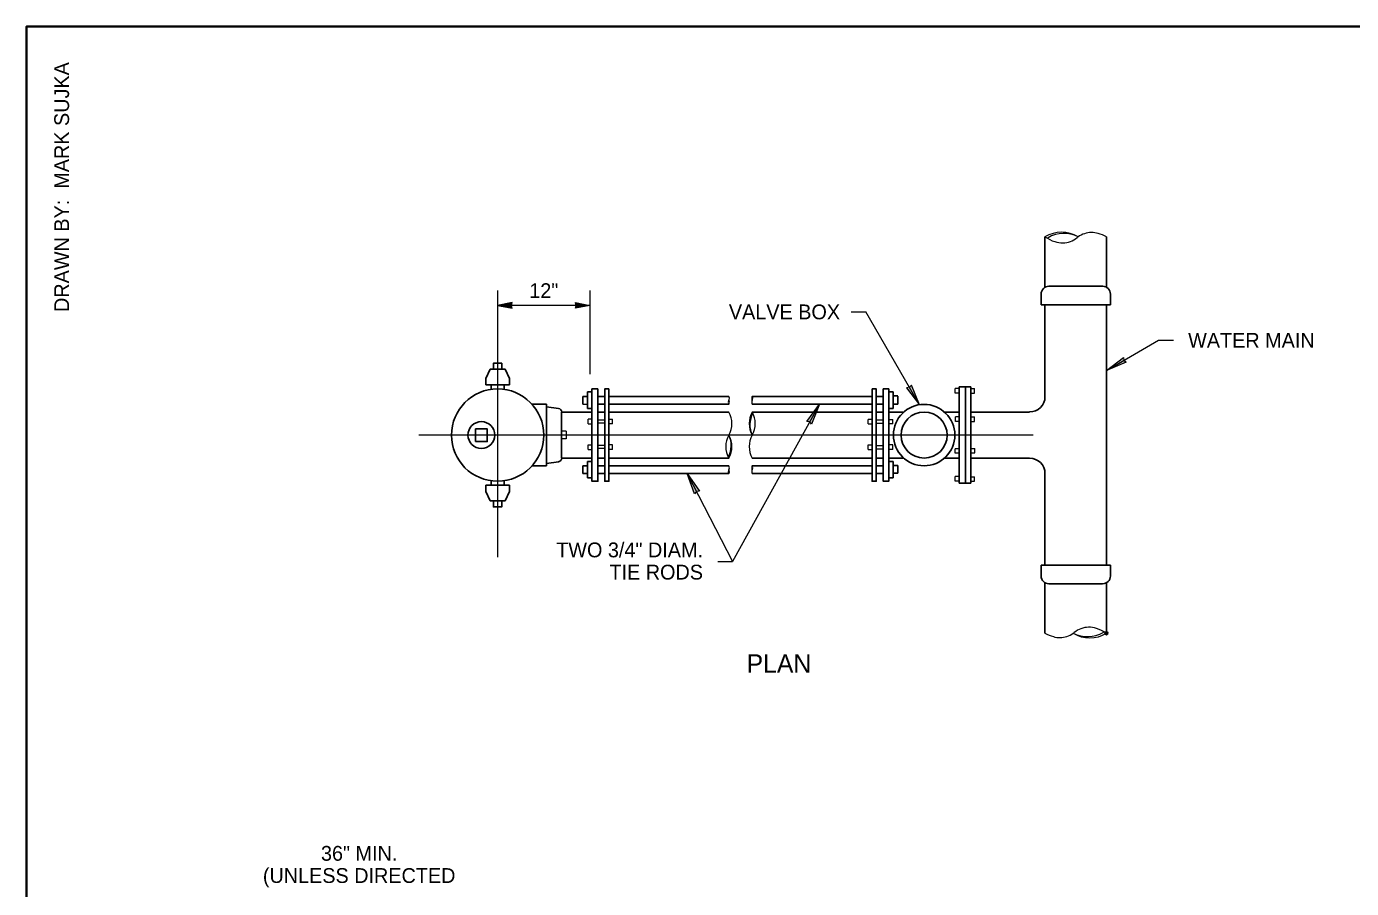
# Model space of a CAD drawing. Extents: x 99860 to 103153, y 99998 to 102077.
# Drawn here: x 99862 to 101294, y 101144 to 102076 of the extents above; entities that cross this region are included whole.
import ezdxf
from ezdxf.enums import TextEntityAlignment as Align

# ---------------------------------------------------------------- set-up
doc = ezdxf.new("R2010")
doc.units = 0
doc.header["$LTSCALE"] = 6.4
doc.header["$PDMODE"] = 32
doc.header["$PDSIZE"] = 3.2
for name, color, linetype, lineweight in [('1', 7, 'Continuous', 25), ('15', 7, 'Continuous', 13), ('18', 7, 'Continuous', 13), ('20', 7, 'Continuous', 13), ('6', 7, 'Continuous', 25)]:
    doc.layers.add(name, color=color, linetype=linetype, lineweight=lineweight)
doc.layers.add('62', color=7, linetype='Continuous')

msp = doc.modelspace()

# ---------------------------------------------------------------- hatches: boundary and pattern name
at = {"layer": '15'}
for points in [[(100371.007, 101774.168), (100386.732, 101771.084), (100386.004, 101774.168), (100386.732, 101777.252)], [(100470.757, 101774.168), (100455.032, 101771.084), (100455.76, 101774.168), (100455.032, 101777.252)], [(101028.745, 101704.029), (101047.023, 101718.028), (101047.599, 101714.914), (101050.008, 101712.858)], [(100826.834, 101666.996), (100818.004, 101688.259), (100815.947, 101685.852), (100812.834, 101685.274)], [(100718.66, 101667.48), (100710.239, 101646.052), (100708.136, 101648.419), (100705.013, 101648.937)], [(100575.94, 101592.518), (100589.049, 101573.59), (100585.912, 101573.162), (100583.742, 101570.856)]]:
    msp.add_hatch(color=256, dxfattribs=at).paths.add_polyline_path(points)

# ---------------------------------------------------------------- linework, layer by layer
at = {"layer": '1', "lineweight": 35}
msp.add_lwpolyline([(99862, 99999.5), (103151, 99999.5), (103151, 102075.5), (99862, 102075.5)], close=True, dxfattribs=at)
at = {"layer": '15'}
for p, q in [((100371.007, 101790.168), (100371.007, 101502.38)), ((100470.757, 101790.168), (100470.757, 101700.105)), ((100470.757, 101774.168), (100371.007, 101774.168)), ((100752.967, 101767.226), (100768.967, 101767.226)), ((100826.834, 101666.996), (100768.967, 101767.226)), ((101028.745, 101704.029), (101085.037, 101736.529)), ((101085.037, 101736.529), (101101.037, 101736.529)), ((100718.66, 101667.48), (100624.853, 101497.568)), ((100285.793, 101634.268), (100949.745, 101634.268)), ((100575.94, 101592.518), (100624.853, 101497.568)), ((100608.853, 101497.568), (100624.853, 101497.568))]:
    msp.add_line(p, q, dxfattribs=at)
for points in [[(100371.007, 101774.168), (100386.732, 101771.084), (100386.004, 101774.168), (100386.732, 101777.252)], [(100470.757, 101774.168), (100455.032, 101771.084), (100455.76, 101774.168), (100455.032, 101777.252)], [(101028.745, 101704.029), (101047.023, 101718.028), (101047.599, 101714.914), (101050.008, 101712.858)], [(100826.834, 101666.996), (100818.004, 101688.259), (100815.947, 101685.852), (100812.834, 101685.274)], [(100718.66, 101667.48), (100710.239, 101646.052), (100708.136, 101648.419), (100705.013, 101648.937)], [(100575.94, 101592.518), (100589.049, 101573.59), (100585.912, 101573.162), (100583.742, 101570.856)]]:
    msp.add_lwpolyline(points, close=True, dxfattribs=at)
at = {"layer": '18', "lineweight": 25}
for p, q in [((100358.232, 101695.455), (100362.77, 101705.293)), ((100358.232, 101688.268), (100358.232, 101695.455)), ((100379.27, 101705.293), (100362.77, 101705.293)), ((100383.77, 101688.268), (100358.232, 101688.268)), ((100363.845, 101683.542), (100363.845, 101688.268)), ((100378.195, 101683.54), (100378.195, 101688.268)), ((100869.72, 101582.405), (100869.72, 101686.143)), ((100869.72, 101686.143), (100882.207, 101686.143)), ((100876.345, 101582.405), (100876.345, 101686.143)), ((100882.207, 101582.405), (100882.207, 101686.143)), ((100408.22, 101667.48), (100423.707, 101667.48)), ((100423.707, 101667.48), (100423.707, 101601.03)), ((100463.207, 101675.993), (100468.232, 101675.993)), ((100463.207, 101675.743), (100463.207, 101667.48)), ((100468.232, 101680.868), (100468.232, 101663.043)), ((100468.232, 101680.868), (100472.882, 101680.868)), ((100479.27, 101675.993), (100486.707, 101675.993)), ((100479.27, 101667.48), (100486.707, 101667.48)), ((100491.207, 101675.993), (100620.77, 101675.993)), ((100491.207, 101667.48), (100620.77, 101667.48)), ((100646.081, 101675.993), (100775.545, 101675.993)), ((100646.081, 101667.48), (100775.545, 101667.48)), ((100787.545, 101675.993), (100780.082, 101675.993)), ((100787.545, 101667.48), (100780.082, 101667.48)), ((100798.42, 101680.868), (100793.77, 101680.868)), ((100798.42, 101663.043), (100798.42, 101680.868)), ((100803.457, 101676.455), (100798.42, 101676.455)), ((100803.457, 101667.693), (100798.42, 101667.693)), ((100803.457, 101667.693), (100803.457, 101676.205)), ((100423.707, 101664.855), (100436.72, 101662.98)), ((100440.145, 101658.968), (100472.882, 101658.968)), ((100440.145, 101658.968), (100440.145, 101609.543)), ((100468.232, 101663.043), (100472.882, 101663.043)), ((100798.42, 101663.043), (100793.77, 101663.043)), ((100408.22, 101601.03), (100423.707, 101601.03)), ((100423.707, 101603.405), (100436.72, 101605.28)), ((100440.145, 101609.268), (100472.882, 101609.268)), ((100463.207, 101601.03), (100468.232, 101601.03)), ((100463.207, 101601.03), (100463.207, 101592.518)), ((100468.232, 101605.718), (100468.232, 101587.893)), ((100468.232, 101605.718), (100472.882, 101605.718)), ((100479.27, 101601.03), (100486.707, 101601.03)), ((100491.207, 101601.03), (100620.806, 101601.03)), ((100646.081, 101601.03), (100775.545, 101601.03)), ((100787.545, 101601.03), (100780.082, 101601.03)), ((100798.42, 101605.718), (100793.77, 101605.718)), ((100798.42, 101587.893), (100798.42, 101605.718)), ((100803.457, 101601.243), (100798.42, 101601.243)), ((100803.457, 101592.98), (100803.457, 101601.243)), ((100363.845, 101584.805), (100363.845, 101580.555)), ((100378.195, 101584.805), (100378.195, 101580.555)), ((100463.207, 101592.518), (100468.232, 101592.518)), ((100468.232, 101587.893), (100472.882, 101587.893)), ((100479.27, 101592.518), (100486.707, 101592.518)), ((100491.207, 101592.518), (100620.806, 101592.518)), ((100646.081, 101592.518), (100775.545, 101592.518)), ((100787.545, 101592.518), (100780.082, 101592.518)), ((100798.42, 101587.893), (100793.77, 101587.893)), ((100803.457, 101592.98), (100798.42, 101592.98)), ((100882.207, 101582.405), (100869.72, 101582.405)), ((100358.232, 101580.243), (100358.232, 101573.093)), ((100383.77, 101580.243), (100358.232, 101580.243)), ((100358.232, 101573.093), (100362.77, 101563.23)), ((100383.77, 101573.093), (100379.27, 101563.23)), ((100383.77, 101580.243), (100383.77, 101573.093)), ((100379.27, 101563.23), (100362.77, 101563.23))]:
    msp.add_line(p, q, dxfattribs=at)
at = {"layer": '18'}
for p, q in [((100869.72, 101684.38), (100865.407, 101684.38)), ((100865.407, 101679.418), (100865.407, 101684.38)), ((100882.207, 101684.38), (100886.345, 101684.38)), ((100886.345, 101679.418), (100886.345, 101684.38)), ((100463.207, 101667.48), (100468.232, 101667.48)), ((100869.72, 101679.418), (100865.407, 101679.418)), ((100882.207, 101679.418), (100886.345, 101679.418)), ((100865.52, 101648.918), (100865.52, 101653.88)), ((100869.72, 101653.88), (100865.52, 101653.88)), ((100882.207, 101653.88), (100886.307, 101653.88)), ((100886.307, 101648.918), (100886.307, 101653.88)), ((100444.982, 101638.28), (100440.145, 101638.28)), ((100472.882, 101651.38), (100468.757, 101651.38)), ((100468.757, 101646.418), (100468.757, 101651.38)), ((100468.757, 101646.418), (100472.882, 101646.418)), ((100479.27, 101650.68), (100486.707, 101650.68)), ((100486.707, 101647.155), (100479.27, 101647.155)), ((100491.207, 101651.38), (100495.182, 101651.38)), ((100495.182, 101646.418), (100491.207, 101646.418)), ((100495.182, 101646.418), (100495.182, 101651.38)), ((100775.545, 101651.168), (100771.445, 101651.168)), ((100771.445, 101646.205), (100771.445, 101651.168)), ((100771.445, 101646.205), (100775.545, 101646.205)), ((100780.045, 101646.943), (100787.507, 101646.943)), ((100787.545, 101650.455), (100780.082, 101650.455)), ((100793.645, 101651.168), (100797.87, 101651.168)), ((100797.87, 101646.205), (100793.645, 101646.205)), ((100797.87, 101646.205), (100797.87, 101651.168)), ((100869.632, 101648.918), (100865.52, 101648.918)), ((100882.207, 101648.918), (100886.307, 101648.918)), ((100468.782, 101623.693), (100472.882, 101623.693)), ((100468.782, 101618.73), (100468.782, 101623.693)), ((100468.782, 101618.73), (100472.882, 101618.73)), ((100486.707, 101622.98), (100479.27, 101622.98)), ((100486.707, 101619.505), (100479.27, 101619.505)), ((100495.207, 101623.693), (100491.207, 101623.693)), ((100495.207, 101618.73), (100491.207, 101618.73)), ((100495.207, 101618.73), (100495.207, 101623.693)), ((100771.407, 101623.48), (100775.545, 101623.48)), ((100771.407, 101618.518), (100771.407, 101623.48)), ((100771.407, 101618.518), (100775.545, 101618.518)), ((100780.082, 101622.768), (100787.545, 101622.768)), ((100780.082, 101619.28), (100787.545, 101619.28)), ((100797.845, 101623.48), (100793.645, 101623.48)), ((100797.845, 101618.518), (100793.645, 101618.518)), ((100797.845, 101618.518), (100797.845, 101623.48)), ((100865.407, 101614.505), (100865.407, 101619.468)), ((100869.72, 101619.468), (100865.407, 101619.468)), ((100869.72, 101614.505), (100865.407, 101614.505)), ((100882.207, 101619.843), (100886.432, 101619.843)), ((100882.207, 101614.88), (100886.432, 101614.88)), ((100886.432, 101614.88), (100886.432, 101619.843)), ((100865.307, 101584.318), (100865.307, 101589.28)), ((100869.72, 101589.28), (100865.307, 101589.28)), ((100869.72, 101584.318), (100865.307, 101584.318)), ((100882.207, 101589.218), (100886.282, 101589.218)), ((100882.207, 101584.255), (100886.282, 101584.255)), ((100886.282, 101584.255), (100886.282, 101589.218))]:
    msp.add_line(p, q, dxfattribs=at)
at = {"layer": '18', "lineweight": 25}
for points in [[(100366.507, 101705.293), (100366.507, 101711.668), (100375.532, 101711.668), (100375.532, 101705.293)], [(100479.27, 101684.005), (100472.882, 101684.005), (100472.882, 101584.255), (100479.27, 101584.255)], [(100491.207, 101684.005), (100486.707, 101684.005), (100486.707, 101584.255), (100491.207, 101584.255)], [(100775.545, 101684.005), (100780.082, 101684.005), (100780.082, 101584.255), (100775.545, 101584.255)], [(100787.545, 101684.005), (100793.645, 101684.005), (100793.645, 101584.255), (100787.545, 101584.255)], [(100347.107, 101627.055), (100347.107, 101640.905), (100359.87, 101640.905), (100359.87, 101627.055)], [(100366.507, 101563.23), (100366.507, 101556.593), (100375.532, 101556.593), (100375.532, 101563.23)]]:
    msp.add_lwpolyline(points, close=True, dxfattribs=at)
msp.add_lwpolyline([(100383.77, 101688.268), (100383.77, 101695.455), (100379.27, 101705.293)], dxfattribs=at)
at = {"layer": '18'}
msp.add_lwpolyline([(100444.982, 101638.28), (100444.982, 101630.018), (100440.145, 101630.018)], dxfattribs=at)
at = {"layer": '18', "lineweight": 25}
for centre, radius in [((100371.012, 101634.192), 49.868), ((100353.459, 101634.192), 14.468)]:
    msp.add_circle(centre, radius, dxfattribs=at)
at = {"layer": '18'}
for centre, start, end in [((100624.456, 101669.608), 150, 210), ((100617.084, 101673.865), 330, 30), ((100617.084, 101669.608), 330, 30), ((100649.767, 101673.865), 150, 210), ((100649.767, 101669.608), 150, 210), ((100642.395, 101673.865), 330, 30), ((100624.492, 101594.646), 150, 210), ((100617.12, 101598.902), 330, 30), ((100617.12, 101594.646), 330, 30), ((100649.767, 101598.902), 150, 210), ((100649.767, 101594.646), 150, 210), ((100642.395, 101598.902), 330, 30)]:
    msp.add_arc(centre, 4.256, start, end, dxfattribs=at)
at = {"layer": '18', "lineweight": 25}
for centre, start, end in [((100436.109, 101658.87), 0, 81.50484), ((100436.109, 101609.515), 278.49516, 0)]:
    msp.add_arc(centre, 4.156, start, end, dxfattribs=at)
at = {"layer": '6'}
for p, q in [((100962.257, 101793.843), (100962.257, 101848.343)), ((101028.745, 101793.843), (101028.745, 101848.343)), ((100958.245, 101774.943), (100958.245, 101786.63)), ((100966.52, 101794.893), (101024.77, 101794.893)), ((101032.995, 101774.943), (101032.995, 101786.63)), ((100958.245, 101774.943), (101032.995, 101774.943)), ((100962.257, 101774.943), (100962.257, 101675.743)), ((101028.745, 101774.943), (101028.745, 101493.593)), ((100479.27, 101658.968), (100486.707, 101658.968)), ((100491.207, 101658.968), (100620.77, 101658.968)), ((100646.081, 101658.968), (100775.545, 101658.968)), ((100780.082, 101658.968), (100787.545, 101658.968)), ((100793.645, 101658.968), (100809.87, 101658.968)), ((100853.745, 101658.968), (100869.682, 101658.968)), ((100882.207, 101658.968), (100945.757, 101658.968)), ((100479.27, 101609.268), (100486.707, 101609.268)), ((100491.207, 101609.268), (100620.806, 101609.268)), ((100646.081, 101609.268), (100775.545, 101609.268)), ((100780.082, 101609.268), (100787.545, 101609.268)), ((100793.645, 101609.268), (100809.87, 101609.268)), ((100853.745, 101609.268), (100869.682, 101609.268)), ((100882.207, 101609.268), (100945.757, 101609.268)), ((100962.257, 101592.518), (100962.257, 101493.593)), ((100958.245, 101493.593), (101032.995, 101493.593)), ((100958.245, 101493.593), (100958.245, 101481.88)), ((101032.995, 101493.593), (101032.995, 101481.88)), ((100962.257, 101474.767), (100962.257, 101420.18)), ((100966.556, 101473.569), (101024.684, 101473.569)), ((101028.745, 101474.629), (101028.745, 101420.18))]:
    msp.add_line(p, q, dxfattribs=at)
for radius in [33.175, 24.864]:
    msp.add_circle((100831.787, 101634.192), radius, dxfattribs=at)
at = {"layer": '6', "lineweight": 13}
for centre, radius, start, end in [((100980.289, 101819.031), 34.304, 58.45293, 121.49802), ((101012.624, 101828.35), 24.569, 90.41519, 125.84404), ((101012.635, 101826.886), 26.033, 74.22175, 90.4152), ((100987.941, 101887.389), 46.728, 236.81818, 251.40013), ((100965.982, 101846.819), 0.601, 116.28667, 233.18686), ((100982.814, 101817.791), 34.155, 63.15572, 120.05018), ((100981.092, 101867.039), 25.256, 251.40013, 271.28062), ((100981.083, 101867.452), 25.669, 271.28062, 308.89129), ((101012.624, 101828.35), 24.569, 125.84404, 128.89129), ((101006.949, 101806.762), 46.945, 62.1809, 74.22175), ((100599.285, 101646.543), 24.85, 330, 30), ((100667.602, 101646.543), 24.85, 150, 210), ((100668.474, 101645.23), 24.999, 150.18317, 206.39347), ((100624.56, 101646.543), 24.85, 330, 30), ((100642.327, 101621.693), 24.85, 150, 210), ((100598.413, 101623.005), 24.999, 330.18317, 26.39347), ((100599.285, 101621.693), 24.85, 330, 30), ((100667.602, 101621.693), 24.85, 150, 210), ((101010.028, 101400.932), 25.669, 91.28062, 128.89129), ((101010.019, 101401.345), 25.256, 71.40013, 91.28062), ((101003.171, 101380.995), 46.728, 56.81818, 71.40013), ((100984.163, 101461.622), 46.945, 242.1809, 254.22175), ((100978.476, 101441.498), 26.033, 254.22175, 270.4152), ((100978.487, 101440.034), 24.569, 270.41519, 305.84404), ((101008.186, 101450.523), 34.042, 243.27016, 300.16462), ((100978.487, 101440.034), 24.569, 305.84404, 308.89129), ((101010.822, 101449.353), 34.304, 238.45292, 301.49802), ((101025.02, 101421.627), 0.601, 296.28667, 53.18686)]:
    msp.add_arc(centre, radius, start, end, dxfattribs=at)
at = {"layer": '6'}
for centre, radius, start, end in [((100966.522, 101786.551), 8.311, 90, 180), ((101024.701, 101786.551), 8.311, 0, 90), ((100945.744, 101675.749), 16.623, 270, 0), ((100945.744, 101592.635), 16.623, 0, 90), ((100966.556, 101481.88), 8.311, 180, 270), ((101024.684, 101481.88), 8.311, 270, 0)]:
    msp.add_arc(centre, radius, start, end, dxfattribs=at)
msp.add_point((101028.745, 101420.103), dxfattribs=at)

# ---------------------------------------------------------------- texts
at = {"layer": '20'}
for s, height, p in [('12"', 16, (100420.885, 101782.168)), ('PLAN', 20, (100674.947, 101377.369)), ('36" MIN.', 16, (100221.404, 101174.385)), ('(UNLESS DIRECTED', 16, (100221.404, 101150.385))]:
    msp.add_text(s, height=height, dxfattribs=at).set_placement(p, align=Align.CENTER)
for s, p in [('VALVE BOX', (100740.97, 101759.226)), ('TWO 3/4" DIAM.', (100592.869, 101502.134)), ('TIE RODS', (100592.868, 101478.134))]:
    msp.add_text(s, height=16, dxfattribs=at).set_placement(p, align=Align.RIGHT)
msp.add_text('WATER MAIN', height=16, dxfattribs=at).set_placement((101117.037, 101728.529))
at = {"layer": '62'}
msp.add_text('DRAWN BY:  MARK SUJKA', height=16, rotation=90, dxfattribs=at).set_placement((99908, 102037.001), align=Align.RIGHT)

doc.saveas('drawing.dxf')
